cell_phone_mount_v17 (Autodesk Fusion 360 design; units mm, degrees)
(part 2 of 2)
extrude "Extrusion10" add sketch "Skizze10" profile of L2 L3 L7 L8 L10 L11 L12 L13 L14 L15 L16 L17 L18 L19 L20 L21 L22 L23 L24 L25 L26 L27 L28 L29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 to an object
sketch "Skizze11" plane through (8.15, 0, 0) normal (-1, 0, 0) x axis (0, -1, 0)
  line L1 (25, -32) -> (14, -32)
  line L2 (25, -10) -> (25, -32)
  line L3 (28.95, -10) -> (25, -10)
  line L4 (28.95, 0) -> (28.95, -10)
  line L5 (-28.95, 0) -> (28.95, 0)
  line L6 (-28.95, -10) -> (-28.95, 0)
  line L7 (-25, -10) -> (-28.95, -10)
  line L8 (-25, -32) -> (-25, -10)
  line L9 (-14, -32) -> (-25, -32)
  line L10 (28.95, -10) -> (32.95, -10)
  line L11 (25, -10) -> (28.95, -10)
  line L12 (28.95, -10) -> (25, -10)
  line L13 (25.95, -10) -> (28.95, -10)
  line L14 (-25.95, -10) -> (25.95, -10)
  line L15 (-28.95, -10) -> (-25.95, -10)
  line L16 (-25, -10) -> (-28.95, -10)
  line L17 (-28.95, -10) -> (-25, -10)
  line L18 (-32.95, -10) -> (-28.95, -10)
  line L19 (-25.95, -10) -> (-32.95, -10)
  line L20 (25.95, -10) -> (-25.95, -10)
  line L21 (32.95, -10) -> (25.95, -10)
  line L22 (-32.95, -10) -> (-25, -32)
  line L23 (32.95, -10) -> (25, -32)
  arc A1 centre (0, -32) radius 14 clockwise from (-14, -32) to (14, -32)
  point P12 (-25, -32)
  point P21 (-25, -32)
  point P20 (-32.95, -10)
  point P22 (-32.95, -10)
  point P5 (25, -32)
  point P23 (25, -32)
  point P13 (32.95, -10)
  point P24 (32.95, -10)
  coincident P12 P21
  coincident P20 P22
  coincident P5 P23
  coincident P13 P24
extrude "Extrusion11" add sketch "Skizze11" profile of L2 L3 L7 L8 L10 L11 L12 L13 L14 L15 L16 L17 L18 L19 L20 L21 L22 L23 to an object
base_feature "Basiselement1"
joint "Zusammenfügen1" alignAngle 0 alignOffsetX 0 alignOffsetY 0 alignOffsetZ 0
copy_paste "Kopieren/Einfügen1"
joint "Zusammenfügen2" alignAngle 0 alignOffsetX 0 alignOffsetY 0 alignOffsetZ 0
copy_paste "Kopieren/Einfügen2"
copy_paste "Kopieren/Einfügen3"
chamfer "Fase1" distance 15
chamfer "Fase2" distance 1
chamfer "Fase5" distance 1
joint "Zusammenfügen3" alignAngle 0 alignOffsetX 0 alignOffsetY 0 alignOffsetZ 0
joint "Zusammenfügen4" alignAngle 0 alignOffsetX 0 alignOffsetY 0 alignOffsetZ 0
base_feature "Basiselement1"
position "Position1"
sketch "Skizze1" plane through (0, 0, 64.15) normal (0, 0, -1) x axis (1, 0, 0)
  line L1 (0, -4.6188) -> (-4, -2.3094)
  line L2 (4, -2.3094) -> (0, -4.6188)
  line L3 (4, 2.3094) -> (4, -2.3094)
  line L4 (0, 4.6188) -> (4, 2.3094)
  line L5 (-4, 2.3094) -> (0, 4.6188)
  line L6 (-4, -2.3094) -> (-4, 2.3094)
  line L7 (4.1, 2.3671) -> (4.1, -2.3671)
  line L8 (0, 4.7343) -> (4.1, 2.3671)
  line L9 (-4.1, 2.3671) -> (0, 4.7343)
  line L10 (-4.1, -2.3671) -> (-4.1, 2.3671)
  line L11 (0, -4.7343) -> (-4.1, -2.3671)
  line L12 (4.1, -2.3671) -> (0, -4.7343)
  arc A1 centre (0, 0) radius 2.5 clockwise from (0, 2.5) to (-1.7678, 1.7678)
  arc A2 centre (0, 0) radius 2.5 clockwise from (-1.7678, 1.7678) to (0, 2.5)
  circle C1 centre (0, 0) radius 11.5
  circle C2 centre (0, 0) radius 2.6
  concentric A1 C1
  concentric A1 C2
  dimension "d141" = 0.1
  dimension "d142" diameter C1 = 23
  dimension "d143" diameter C2 = 5.2
extrude "Extrusion1" new body sketch "Skizze1" profile of L1 L2 L3 L4 L5 L6 L7 L11 L8 L9 L10 L12 C1 C2 along normal blind 2
extrude "Extrusion2" add sketch "Skizze1" profile of L7 L11 L8 L9 L10 L12 C1 to an object offset 1
sketch "Skizze2" plane through (0, 0, 68.85) normal (0, 0, 1) x axis (-1, 0, 0)
  line L1 (0, -4.7343) -> (4.1, -2.3671)
  line L2 (-4.1, -2.3671) -> (0, -4.7343)
  line L3 (-4.1, 2.3671) -> (-4.1, -2.3671)
  line L4 (0, 4.7343) -> (-4.1, 2.3671)
  line L5 (4.1, 2.3671) -> (0, 4.7343)
  line L6 (4.1, -2.3671) -> (4.1, 2.3671)
  circle C1 centre (0, 0) radius 11.5
extrude "Extrusion3" new body sketch "Skizze2" along normal blind 2
chamfer "Fase1" distance 2
sketch "Skizze3" plane through (0, 0, 68.85) normal (0, 0, -1) x axis (1, 0, 0)
  line L1 (0, -4.6188) -> (-4, -2.3094)
  line L2 (4, -2.3094) -> (0, -4.6188)
  line L3 (4, 2.3094) -> (4, -2.3094)
  line L4 (0, 4.6188) -> (4, 2.3094)
  line L5 (-4, 2.3094) -> (0, 4.6188)
  line L6 (-4, -2.3094) -> (-4, 2.3094)
  line L7 (4.1, 2.3671) -> (4.1, -2.3671)
  line L8 (0, 4.7343) -> (4.1, 2.3671)
  line L9 (-4.1, 2.3671) -> (0, 4.7343)
  line L10 (-4.1, -2.3671) -> (-4.1, 2.3671)
  line L11 (0, -4.7343) -> (-4.1, -2.3671)
  line L12 (4.1, -2.3671) -> (0, -4.7343)
  circle C1 centre (0, 0) radius 11.5
  arc A1 centre (0, 0) radius 2.5 clockwise from (0, 2.5) to (-1.7678, 1.7678)
  arc A2 centre (0, 0) radius 2.5 clockwise from (-1.7678, 1.7678) to (0, 2.5)
  dimension "d151" = 0.1
extrude "Extrusion4" add sketch "Skizze3" profile of L1 L2 L3 L4 L5 L6 A1 A2 L7 L12 L8 L10 L9 L11 to an object offset 0.2
sketch "Skizze4" plane through (0, 0, 70.85) normal (0, 0, 1) x axis (-1, 0, 0)
  circle C1 centre (0, 0) radius 9.5
  circle C2 centre (0, 0) radius 11.5
  circle C3 centre (0, 0) radius 9.5
  circle C4 centre (0.1997, -11.4983) radius 2
  circle C5 centre (6.3844, -9.565) radius 2
  circle C6 centre (10.5421, -4.5949) radius 2
  circle C7 centre (11.3528, 1.834) radius 2
  circle C8 centre (8.559, 7.6807) radius 2
  circle C9 centre (3.0478, 11.0888) radius 2
  circle C10 centre (-3.431, 10.9762) radius 2
  circle C11 centre (-8.8206, 7.3789) radius 2
  circle C12 centre (-11.4096, 1.4387) radius 2
  circle C13 centre (-10.3762, -4.9582) radius 2
  circle C14 centre (-6.0485, -9.7809) radius 2
  point P4 (0.1997, -11.4983)
  coincident C2 P4
  tangent C3 C4
  dimension "d155" C-Pattern1-Angle = 360
extrude "Extrusion5" cut sketch "Skizze4" profile of C2 C4 C5 C6 C7 C8 C9 C10 C11 C12 C13 C14 to an object
as_built_joint "Bestand"
joint "Zusammenfügen5" alignAngle 0 alignOffsetX 0 alignOffsetY 0 alignOffsetZ 0
sketch "Skizze9" plane through (0, 0, 0) normal (0, 0, -1) x axis (1, 0, 0)
  line L1 (-81.55, -19.4258) -> (-79.15, -19.4258)
  line L2 (-81.55, -25.95) -> (-81.55, -19.4258)
  line L3 (64.65, -42.85) -> (-64.65, -42.85)
  line L4 (83.0698, -29.95) -> (80.4823, -31.8618)
  line L5 (78.5874, -29.95) -> (83.0698, -29.95)
  line L6 (-64.65, -40.45) -> (64.65, -40.45)
  line L7 (-79.15, -19.4258) -> (-79.15, -25.95)
  line L8 (-47.75, -51.3197) -> (-5.75, -51.3197)
  line L9 (-47.75, -30.3731) -> (-47.75, -51.3197)
  line L10 (-5.75, -30.3731) -> (-47.75, -30.3731)
  line L11 (-5.75, -51.3197) -> (-5.75, -30.3731)
  line L12 (-75.75, -25.95) -> (-75.75, 25.95)
  line L13 (79.1486, 26.15) -> (75.7482, 26.15)
  line L14 (-64.65, 40.45) -> (64.65, 40.45)
  line L15 (-79.15, 19.4258) -> (-79.15, 25.95)
  line L16 (-81.55, 19.4258) -> (-79.15, 19.4258)
  line L17 (-81.55, 19.2258) -> (-81.55, 19.4258)
  line L18 (-95.35, 11.2583) -> (-81.55, 19.2258)
  line L19 (-81.55, -19.2258) -> (-95.35, -11.2583)
  line L20 (-81.55, -19.4258) -> (-81.55, -19.2258)
  line L21 (-79.15, -19.4258) -> (-81.55, -19.4258)
  line L22 (-79.15, -25.95) -> (-79.15, -19.4258)
  line L23 (64.65, -40.45) -> (-64.65, -40.45)
  line L24 (75.7482, -26.15) -> (79.1486, -26.15)
  line L25 (-64.65, -37.05) -> (64.65, -37.05)
  line L26 (-75.75, 25.95) -> (-75.75, -25.95)
  line L27 (64.65, 37.05) -> (-64.65, 37.05)
  arc A1 centre (-64.65, -25.95) radius 16.9 clockwise from (-64.65, -42.85) to (-81.55, -25.95)
  arc A2 centre (64.65, -25.95) radius 16.9 clockwise from (80.4823, -31.8618) to (64.65, -42.85)
  arc A3 centre (64.65, -25.95) radius 14.5 clockwise from (78.5874, -29.95) to (64.65, -40.45)
  arc A4 centre (-64.65, -25.95) radius 14.5 clockwise from (-64.65, -40.45) to (-79.15, -25.95)
  circle C1 centre (-88.85, 0) radius 3
  arc A5 centre (64.65, 25.95) radius 14.5 clockwise from (64.65, 40.45) to (79.1486, 26.15)
  arc A6 centre (-64.65, 25.95) radius 14.5 clockwise from (-79.15, 25.95) to (-64.65, 40.45)
  arc A7 centre (-88.85, 0) radius 13 clockwise from (-95.35, -11.2583) to (-95.35, 11.2583)
  arc A8 centre (-64.65, -25.95) radius 14.5 clockwise from (-64.65, -40.45) to (-79.15, -25.95)
  arc A9 centre (64.65, -25.95) radius 14.5 clockwise from (79.1486, -26.15) to (64.65, -40.45)
  arc A10 centre (64.65, -25.95) radius 11.1 clockwise from (75.7482, -26.15) to (64.65, -37.05)
  arc A11 centre (-64.65, -25.95) radius 11.1 clockwise from (-64.65, -37.05) to (-75.75, -25.95)
  arc A12 centre (-64.65, 25.95) radius 11.1 clockwise from (-75.75, 25.95) to (-64.65, 37.05)
  arc A13 centre (64.65, 25.95) radius 11.1 clockwise from (64.65, 37.05) to (75.7482, 26.15)
  horizontal L8
  vertical L9
  horizontal L10
  vertical L11
  dimension "d162" distance L9 L12 = 28
  dimension "d163" distance L11 L12 = 70
extrude "Extrusion9" cut sketch "Skizze9" profile of L3 L6 L8 L9 L10 L11 L23 L25 to an object
sketch "Skizze10" plane through (0, 0, 0) normal (0, 0, -1) x axis (1, 0, 0)
  line L1 (79.15, -15.75) -> (75.75, -15.75)
  line L2 (79.15, 15.75) -> (79.15, -15.75)
  line L3 (75.75, 15.75) -> (79.15, 15.75)
  line L4 (75.75, -15.75) -> (75.75, 15.75)
  line L5 (87.5946, 8) -> (62.3656, 8)
  line L6 (87.5946, -8) -> (87.5946, 8)
  line L7 (62.3656, -8) -> (87.5946, -8)
  line L8 (62.3656, 8) -> (62.3656, -8)
  line L9 (139.1677, 0) -> (0, 0)
  point P1 (0, 0)
  point P10 (0, 0)
  point P7 (87.5946, 8)
  point P8 (87.5946, -8)
  horizontal L5
  vertical L6
  horizontal L7
  vertical L8
  coincident P1 P10
  horizontal L9
  symmetric L5 L7 L9
  dimension "d167" distance P7 P8 = 16
extrude "Extrusion10" cut sketch "Skizze10" profile of L2 L4 L5 L6 L7 L8 to an object
chamfer "Fase3" distance 1.6
sketch "Skizze11" plane through (0, 0, 11.3) normal (0, 0, 1) x axis (-1, 0, 0)
  line L1 (78.55, -17.4937) -> (78.55, -25.95)
  line L2 (93.85, -8.6603) -> (78.55, -17.4937)
  line L3 (78.55, 17.4937) -> (93.85, 8.6603)
  line L4 (78.55, 25.95) -> (78.55, 17.4937)
  line L5 (-64.65, 39.85) -> (64.65, 39.85)
  line L6 (-78.55, -25.95) -> (-78.55, 25.95)
  line L7 (64.65, -39.85) -> (-64.65, -39.85)
  line L8 (72.45, -25.95) -> (72.45, 25.95)
  line L9 (-64.65, -33.75) -> (64.65, -33.75)
  line L10 (-72.45, 25.95) -> (-72.45, -25.95)
  line L11 (64.65, 33.75) -> (-64.65, 33.75)
  line L12 (47.75, -42.85) -> (47.75, -41.85)
  line L13 (64.65, -42.85) -> (47.75, -42.85)
  line L14 (64.65, -39.85) -> (64.65, -42.85)
  line L15 (-64.65, -39.85) -> (64.65, -39.85)
  line L16 (-64.65, -42.85) -> (-64.65, -39.85)
  line L17 (5.75, -42.85) -> (-64.65, -42.85)
  line L18 (5.75, -41.85) -> (5.75, -42.85)
  line L19 (47.75, -41.85) -> (5.75, -41.85)
  line L20 (5.75, -42.85) -> (47.75, -42.85)
  line L21 (5.75, -39.85) -> (5.75, -42.85)
  line L22 (47.75, -39.85) -> (5.75, -39.85)
  line L23 (47.75, -42.85) -> (47.75, -39.85)
  arc A1 centre (88.85, 0) radius 10 clockwise from (93.85, 8.6603) to (93.85, -8.6603)
  arc A2 centre (64.65, 25.95) radius 13.9 clockwise from (64.65, 39.85) to (78.55, 25.95)
  arc A3 centre (-64.65, 25.95) radius 13.9 clockwise from (-78.55, 25.95) to (-64.65, 39.85)
  arc A4 centre (-64.65, -25.95) radius 13.9 clockwise from (-64.65, -39.85) to (-78.55, -25.95)
  arc A5 centre (64.65, -25.95) radius 13.9 clockwise from (78.55, -25.95) to (64.65, -39.85)
  circle C1 centre (88.85, 0) radius 3
  arc A6 centre (64.65, -25.95) radius 7.8 clockwise from (72.45, -25.95) to (64.65, -33.75)
  arc A7 centre (-64.65, -25.95) radius 7.8 clockwise from (-64.65, -33.75) to (-72.45, -25.95)
  arc A8 centre (-64.65, 25.95) radius 7.8 clockwise from (-72.45, 25.95) to (-64.65, 33.75)
  arc A9 centre (64.65, 25.95) radius 7.8 clockwise from (64.65, 33.75) to (72.45, 25.95)
  point P37 (5.75, -39.85)
  point P28 (47.75, -42.85)
  point P35 (47.75, -42.85)
  point P34 (5.75, -41.85)
  horizontal L20
  vertical L21
  horizontal L22
  vertical L23
  coincident L15 P37
  coincident P28 P35
  coincident P34 L21
extrude "Extrusion11" cut sketch "Skizze11" profile of L7 L12 L15 L18 L19 L20 L21 L22 L23 against normal blind 5
chamfer "Fase4" distance 2.4
sketch "Skizze12" plane through (0, 0, 11.3) normal (0, 0, 1) x axis (-1, 0, 0)
  line L1 (78.55, -17.4937) -> (78.55, -25.95)
  line L2 (93.85, -8.6603) -> (78.55, -17.4937)
  line L3 (78.55, 17.4937) -> (93.85, 8.6603)
  line L4 (78.55, 25.95) -> (78.55, 17.4937)
  line L5 (-64.65, 39.85) -> (64.65, 39.85)
  line L6 (-78.55, -25.95) -> (-78.55, 25.95)
  line L7 (5.75, -39.85) -> (-64.65, -39.85)
  line L8 (47.75, -39.85) -> (5.75, -39.85)
  line L9 (64.65, -39.85) -> (47.75, -39.85)
  line L10 (72.45, -25.95) -> (72.45, 25.95)
  line L11 (-64.65, -33.75) -> (64.65, -33.75)
  line L12 (-72.45, 25.95) -> (-72.45, -25.95)
  line L13 (64.65, 33.75) -> (-64.65, 33.75)
  line L14 (-81.55, -8) -> (-80.55, -8)
  line L15 (-81.55, -25.95) -> (-81.55, -8)
  line L16 (-78.55, -25.95) -> (-81.55, -25.95)
  line L17 (-78.55, 25.95) -> (-78.55, -25.95)
  line L18 (-81.55, 25.95) -> (-78.55, 25.95)
  line L19 (-81.55, 8) -> (-81.55, 25.95)
  line L20 (-80.55, 8) -> (-81.55, 8)
  line L21 (-80.55, -8) -> (-80.55, 8)
  line L22 (-80.15, -8) -> (-81.55, -8)
  line L23 (-80.15, 8) -> (-80.15, -8)
  line L24 (-81.55, 8) -> (-80.15, 8)
  line L25 (-81.55, -8) -> (-81.55, 8)
  arc A1 centre (88.85, 0) radius 10 clockwise from (93.85, 8.6603) to (93.85, -8.6603)
  arc A2 centre (64.65, 25.95) radius 13.9 clockwise from (64.65, 39.85) to (78.55, 25.95)
  arc A3 centre (-64.65, 25.95) radius 13.9 clockwise from (-78.55, 25.95) to (-64.65, 39.85)
  arc A4 centre (-64.65, -25.95) radius 13.9 clockwise from (-64.65, -39.85) to (-78.55, -25.95)
  arc A5 centre (64.65, -25.95) radius 13.9 clockwise from (78.55, -25.95) to (64.65, -39.85)
  circle C1 centre (88.85, 0) radius 3
  arc A6 centre (64.65, -25.95) radius 7.8 clockwise from (72.45, -25.95) to (64.65, -33.75)
  arc A7 centre (-64.65, -25.95) radius 7.8 clockwise from (-64.65, -33.75) to (-72.45, -25.95)
  arc A8 centre (-64.65, 25.95) radius 7.8 clockwise from (-72.45, 25.95) to (-64.65, 33.75)
  arc A9 centre (64.65, 25.95) radius 7.8 clockwise from (64.65, 33.75) to (72.45, 25.95)
  point P30 (-81.55, -8)
  point P37 (-81.55, -8)
  horizontal L22
  vertical L23
  horizontal L24
  vertical L25
  coincident P30 P37
  dimension "d175" distance L21 L23 = 0.4
extrude "Extrusion12" cut sketch "Skizze12" profile of L21 L22 L23 L24 against normal blind 3
chamfer "Fase5" distance 1.4
chamfer "Fase6" distance 0.4
chamfer "Fase7" distance 0.6
sketch "Skizze5" plane through (0, 0, 70.85) normal (0, 0, 1) x axis (-1, 0, 0)
  arc A1 centre (0, 0) radius 9.5 clockwise from (-8.5717, -4.0959) to (-9.4254, 1.1885)
  arc A2 centre (0, 0) radius 9.5 clockwise from (-4.9965, -8.0799) to (-8.5717, -4.0959)
  arc A3 centre (0, 0) radius 9.5 clockwise from (0.165, -9.4986) to (-4.9965, -8.0799)
  arc A4 centre (0, 0) radius 9.5 clockwise from (5.2741, -7.9015) to (0.165, -9.4986)
  arc A5 centre (0, 0) radius 9.5 clockwise from (8.7087, -3.7958) to (5.2741, -7.9015)
  arc A6 centre (0, 0) radius 9.5 clockwise from (9.3784, 1.5151) to (8.7087, -3.7958)
  arc A7 centre (0, 0) radius 9.5 clockwise from (7.0705, 6.3449) to (9.3784, 1.5151)
  arc A8 centre (0, 0) radius 9.5 clockwise from (2.5178, 9.1603) to (7.0705, 6.3449)
  arc A9 centre (0, 0) radius 9.5 clockwise from (-2.8343, 9.0673) to (2.5178, 9.1603)
  arc A10 centre (0, 0) radius 9.5 clockwise from (-7.2866, 6.0956) to (-2.8343, 9.0673)
  arc A11 centre (0, 0) radius 9.5 clockwise from (-9.4254, 1.1885) to (-7.2866, 6.0956)
  circle C1 centre (0, 0) radius 6.5
  concentric A1 C1
  dimension "d180" distance A2 C1 = 3
split "Teilen1"
combine "Kombinieren"
extrude "Extrusion6" cut of existing geometry blind -0.2
chamfer "Fase2" distance 0.6
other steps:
base_feature "Basiselement1" sketch "Skizze6"
thread "Gewinde1"
extrude "Extrusion6" cut sketch "Skizze6" profile of L1 L2 L3 L4 L8 L9 L10 L11 L12 L13 L14 L15 L16 L17 L18 L19 L20 L21 L22 L23 L24 against normal blind 12
create_component "Komponente erstellen1" sketch "Skizze6"
place_component sketch "Skizze6"
remove_body "Körper entfernen1"
create_component "Komponente erstellen2"
create_component "Komponente erstellen3"
create_component "Komponente erstellen4"
create_component "Komponente erstellen5"
joint_origin "Gelenkursprung1"
joint_origin "Gelenkursprung1"
joint_origin "Gelenkursprung2"
joint_origin "Gelenkursprung2"
joint_origin "Gelenkursprung3"
joint_origin "Gelenkursprung3"
joint_origin "Gelenkursprung4"
joint_origin "Gelenkursprung4"
create_component "Komponente erstellen6"
create_component "Komponente erstellen7"
joint_origin "Gelenkursprung1"
joint_origin "Gelenkursprung1"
